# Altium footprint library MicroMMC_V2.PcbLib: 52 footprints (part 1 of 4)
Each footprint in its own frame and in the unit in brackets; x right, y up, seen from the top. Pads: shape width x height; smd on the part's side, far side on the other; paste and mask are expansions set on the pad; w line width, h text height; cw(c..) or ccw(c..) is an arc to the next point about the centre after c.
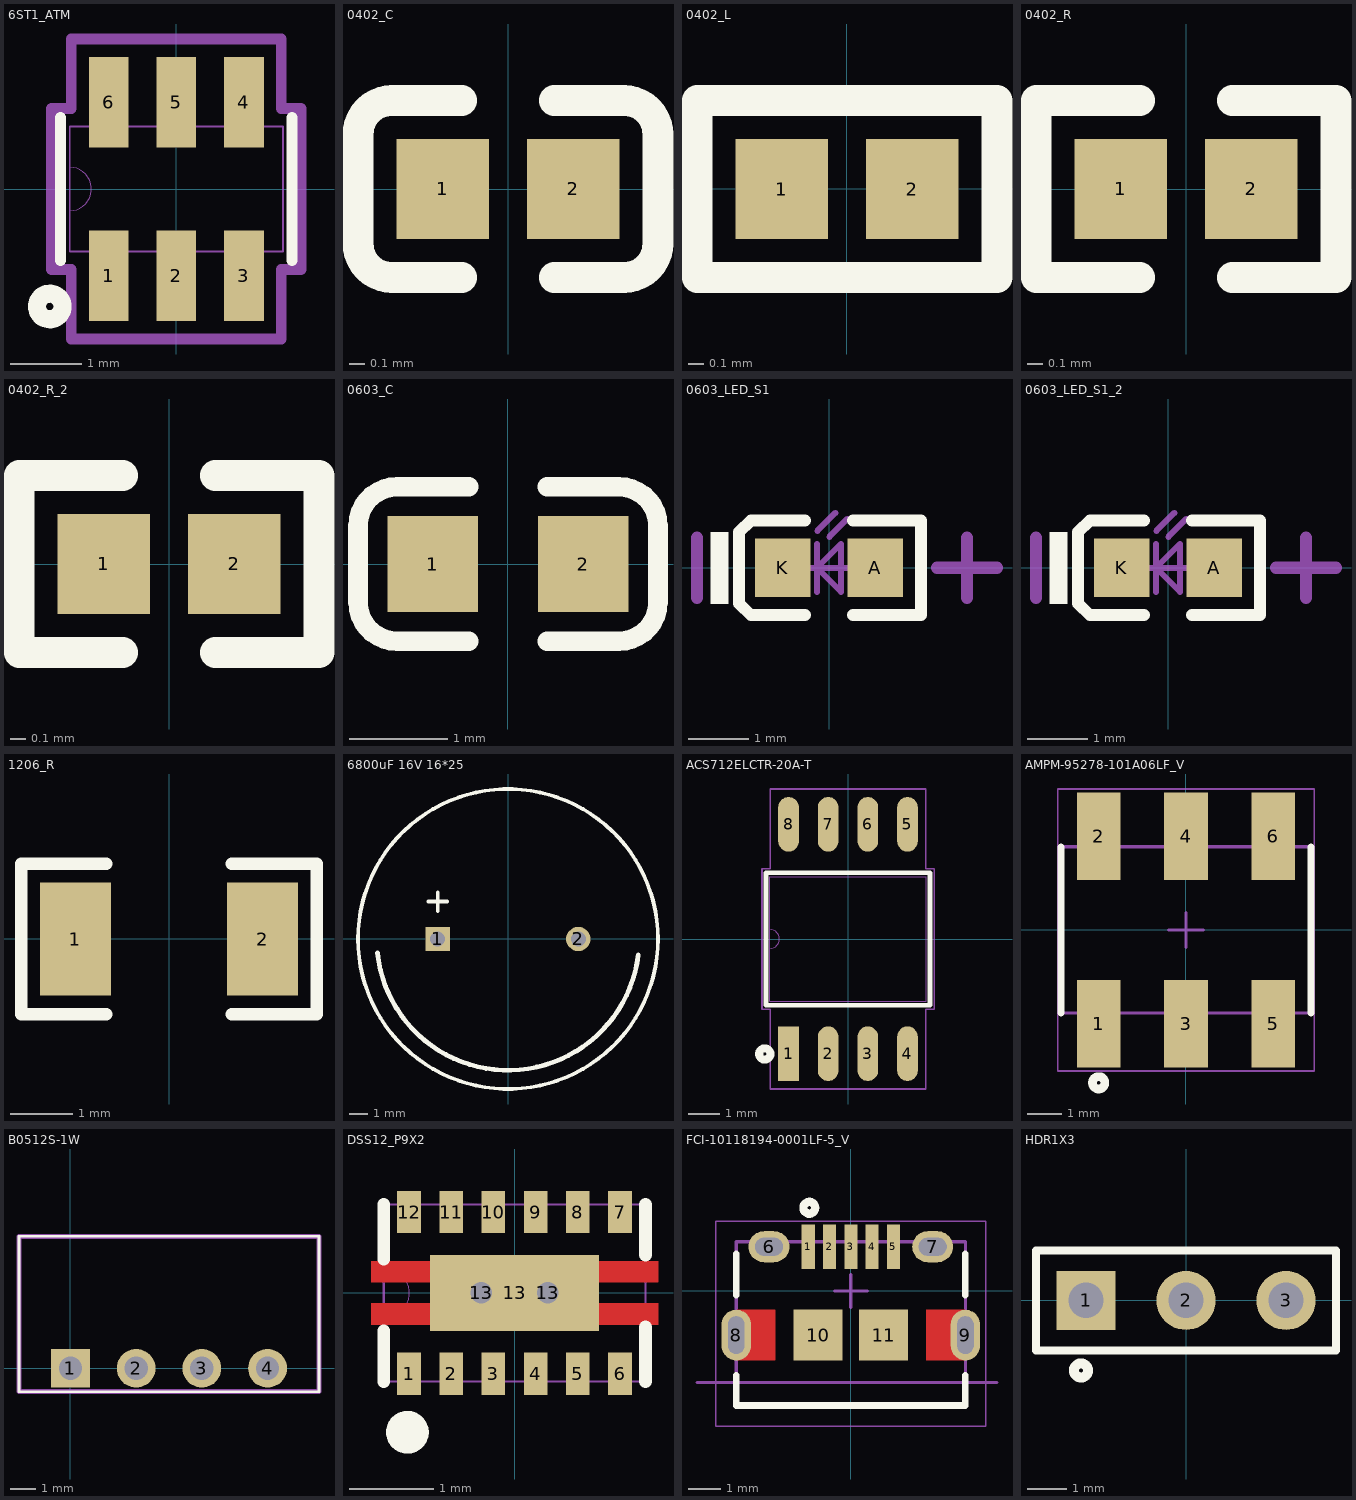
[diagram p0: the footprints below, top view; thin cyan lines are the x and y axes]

## 6ST1_ATM [mil] "ATTINY10"
pads (6):
  rect 22x50 smd: 1(-37.4,-48) 2(0,-48) 3(37.4,-48) 4(37.4,48) 5(0,48) 6(-37.4,48)
Top Overlay:
  circle w10: c-70,-65 r7.07
  lines w6: -64,-39.5 -64,39.5 ; 64,-39.5 64,39.5
Mechanical 13:
  lines w0: -59,-12 ccw(c-59,0) -59,12
  lines w1: -59,-34.5 -59,34.5 59,34.5 59,-34.5 -59,-34.5 ; -47.4,-59 -47.4,-34.5 -27.4,-34.5 -27.4,-59 -47.4,-59 ; -47.4,34.5 -27.4,34.5 -27.4,59 -47.4,59 -47.4,34.5 ; -10,-59 -10,-34.5 10,-34.5 10,-59 -10,-59 ; -10,34.5 10,34.5 10,59 -10,59 -10,34.5 ; 27.4,-59 27.4,-34.5 47.4,-34.5 47.4,-59 27.4,-59 ; 27.4,34.5 47.4,34.5 47.4,59 27.4,59 27.4,34.5
Mechanical 15:
  lines w6: -69,-44.5 -58.1,-44.5 -58.1,-83 58.1,-83 58.1,-44.5 69,-44.5 69,44.5 58.1,44.5 58.1,83 -58.1,83 -58.1,44.5 -69,44.5 -69,-44.5
3D body: height 10, standoff 0, extent -10,0 0,10
3D body "6ST1_ATM.step": height 58.11, standoff 0, extent -59.02,-59.01 59.01,59.02

## 0402_C [mm]
pads (2):
  rect 0.6x0.65 smd mask+0.051: 1(-0.425,0) 2(0.425,0)
Top Overlay:
  lines w0.2: -0.755,-0.575 cw(c-0.755,-0.355) -0.975,-0.355 -0.975,0.355 cw(c-0.755,0.355) -0.755,0.575 ; -0.75,-0.575 -0.3,-0.575 ; -0.75,0.575 -0.3,0.575 ; 0.3,-0.575 0.75,-0.575 ; 0.3,0.575 0.75,0.575 ; 0.755,-0.575 ccw(c0.755,-0.355) 0.975,-0.355 0.975,0.355 ccw(c0.755,0.355) 0.755,0.575
3D body "0402 SMD Capacitor.step": height 0.2, standoff 0, extent -0.483,-0.3 0.518,0.3

## 0402_L [mm]
pads (2):
  rect 0.6x0.65 smd: 1(-0.425,0) 2(0.425,0)
Top Overlay:
  lines w0.2: -0.975,-0.575 -0.975,0.575 0.975,0.575 0.975,-0.575 -0.975,-0.575
3D body "L0402.STEP": height 0.36, standoff -0.01, extent -0.49,-0.262 0.515,0.263

## 0402_R [mm]
pads (2):
  rect 0.6x0.65 smd mask+0.051: 1(-0.425,0) 2(0.425,0)
Top Overlay:
  lines w0.2: -0.3,-0.575 -0.975,-0.575 -0.975,0.575 -0.3,0.575 ; 0.3,-0.575 0.975,-0.575 0.975,0.575 0.3,0.575
3D body "User Library-RES_1005-0402.STEP": height 0.41, standoff 0, extent -0.575,-0.275 0.575,0.275

## 0402_R_2 [mm]
pads (2):
  rect 0.6x0.65 smd mask+0.051: 1(-0.425,0) 2(0.425,0)
Top Overlay:
  lines w0.2: -0.3,-0.575 -0.975,-0.575 -0.975,0.575 -0.3,0.575 ; 0.3,-0.575 0.975,-0.575 0.975,0.575 0.3,0.575
3D body "User Library-RES_1005-0402.STEP": height 0.41, standoff 0, extent -0.575,-0.275 0.575,0.275

## 0603_C [mm]
pads (2):
  rect 0.93x0.98 smd: 1(-0.77,0) 2(0.77,0)
Top Overlay:
  lines w0.2: -0.4,-0.79 -1.135,-0.79 cw(c-1.135,-0.39) -1.535,-0.39 -1.535,0.39 cw(c-1.135,0.39) -1.135,0.79 -0.4,0.79 ; 0.4,-0.79 1.135,-0.79 ccw(c1.135,-0.39) 1.535,-0.39 1.535,0.39 ccw(c1.135,0.39) 1.135,0.79 0.4,0.79
3D body "User Library-0603 SMD Capacitor.STEP": height 0.3, standoff 0, extent -0.8,-0.4 0.8,0.4

## 0603_LED_S1 [mm]
pads (2):
  rect 0.93x0.98 smd: A(0.77,0) K(-0.77,0)
Top Overlay:
  rectangle: -1.975,-0.6 -1.675,0.6
  lines w0.2: -0.4,-0.79 -1.3,-0.79 -1.5,-0.597 -1.5,0.597 -1.3,0.79 -0.4,0.79 ; 0.4,-0.79 1.535,-0.79 1.535,0.79 0.4,0.79
Mechanical 13:
  lines w0.1: -0.4,0 0.4,0 ; -0.2,-0.4 -0.2,0.4 ; -0.195,0.617 0.105,0.917 ; 0.005,0.517 0.305,0.817 ; -0.2,0 0.2,-0.4 0.2,0.4 -0.2,0
Mechanical 15:
  lines w0.203: -2.2,-0.5 -2.2,0.5 ; 1.8,0 2.8,0 ; 2.3,-0.5 2.3,0.5
3D body "User Library-LED_0603_R.STEP": height 0.6, standoff 0, extent -0.8,-0.4 0.8,0.4

## 0603_LED_S1_2 [mm]
pads (2):
  rect 0.93x0.98 smd: A(0.77,0) K(-0.77,0)
Top Overlay:
  rectangle: -1.975,-0.6 -1.675,0.6
  lines w0.2: -0.4,-0.79 -1.3,-0.79 -1.5,-0.597 -1.5,0.597 -1.3,0.79 -0.4,0.79 ; 0.4,-0.79 1.535,-0.79 1.535,0.79 0.4,0.79
Mechanical 13:
  lines w0.1: -0.4,0 0.4,0 ; -0.2,-0.4 -0.2,0.4 ; -0.195,0.617 0.105,0.917 ; 0.005,0.517 0.305,0.817 ; -0.2,0 0.2,0.4 0.2,-0.4 -0.2,0
Mechanical 15:
  lines w0.203: -2.2,-0.5 -2.2,0.5 ; 1.8,0 2.8,0 ; 2.3,-0.5 2.3,0.5
3D body "User Library-LED_0603_R.STEP": height 0.6, standoff 0, extent -0.8,-0.4 0.8,0.4

## 1206_R [mm]
pads (2):
  rect 1.13x1.8 smd: 1(-1.49,0) 2(1.49,0)
Top Overlay:
  lines w0.2: -1,-1.2 -2.355,-1.2 -2.355,1.2 -1,1.2 ; 1,-1.2 2.355,-1.2 2.355,1.2 1,1.2
3D body "User Library-RES_3216-1206.STEP": height 0.85, standoff 0, extent -1.7,-0.864 1.65,0.866

## 6800uF 16V 16*25 [mm] "LCSC C47893"
pads (2):
  rect 1.3x1.3 hole 0.8: 1(-3.75,0)
  round 1.3 hole 0.8: 2(3.75,0)
Top Overlay:
  circle w0.2: c0,0 r8
  lines w0.2: -4.25,2 -3.25,2 ; -3.75,1.5 -3.75,2.5
  lines w0.254: -6.96,-0.743 ccw(c0,0) 6.949,-0.844
3D body "ESK688M010AM2AA v1.step": height 32.01, standoff -19.99, extent -8,-8 8,8

## ACS712ELCTR-20A-T [mil]
pads (8):
  rect 26x69 smd paste+0 mask+0: 1(-75,-144.69)
  oval 26x69 smd paste+0 mask+0: 2(-25,-144.69) 3(25,-144.69) 4(75,-144.69) 5(75,144.69) 6(25,144.69) 7(-25,144.69) 8(-75,144.69)
Top Overlay:
  circle w10: c-105,-145 r7.07
  lines w6: -103.5,-83.5 -103.5,83.5 103.5,83.5 103.5,-83.5 -103.5,-83.5
Mechanical 13:
  lines w0: -98.5,-12 ccw(c-98.5,0) -98.5,12
  lines w1: -98.5,-78.5 -98.5,78.5 98.5,78.5 98.5,-78.5 -98.5,-78.5
Mechanical 15:
  lines w1.97: -108.5,-88.5 -108.5,88.5 -98,88.5 -98,189.19 98,189.19 98,88.5 108.5,88.5 108.5,-88.5 98,-88.5 98,-189.19 -98,-189.19 -98,-88.5 -108.5,-88.5
3D body "SOIC-8_ALM.step": height 69.09, standoff 0, extent -98.5,-170.4 98.5,160.39
3D body "SOIC-8_ALM.step": height 69.09, standoff 0, extent -98.5,-165.4 98.5,165.4
3D body "SOIC-8_ALM.step": height 69.09, standoff 0, extent -98.5,-165.39 98.5,165.4
3D body "SOIC-8_ALM.step": height 69.09, standoff 0, extent -98.5,-165.4 98.5,165.4
3D body: height 10, standoff 0, extent -10,0 0,10

## AMPM-95278-101A06LF_V [mil] "SMD, 6-Leads, Body 7.26x4.83mm, Pitch 2.54mm"
height 566.93
pads (6):
  rect 50x100 smd: 1(-100,-107.48) 2(-100,107.48) 3(0,-107.48) 4(0,107.48) 5(100,-107.48) 6(100,107.48)
Top Overlay:
  circle w10: c-100,-175 r7.07
  lines w7.87: -142.91,-95.08 -142.91,95.08 ; 142.91,-95.08 142.91,95.08
Mechanical 13:
  lines w3.94: -142.91,-95.08 -142.91,95.08 142.91,95.08 142.91,-95.08 -142.91,-95.08
Mechanical 15:
  lines w1.97: -146.85,-161.42 -146.85,161.42 146.85,161.42 146.85,-161.42 -146.85,-161.42
  lines w3.94: -19.68,0 19.68,0 ; 0,-19.68 0,19.69
3D body "95278_y01_06_asm.stp": height 382.38, standoff 1.99, extent -142.13,-143.43 142.12,143.42

## B0512S-1W [mm]
pads (4):
  rect 1.5x1.5 hole 0.9: 1(0,0)
  round 1.5 hole 0.9: 2(2.54,0) 3(5.08,0) 4(7.62,0)
Top Overlay:
  lines w0.1: -1.99,-0.9 -1.99,5.1 9.61,5.1 9.61,-0.9 -1.99,-0.9
Mechanical 13:
  lines w0.2: -1.99,-0.9 -1.99,5.1 9.61,5.1 9.61,-0.9 -1.99,-0.9
3D body "ROE-0512S.stp": height 10.6, standoff -5, extent -1.94,-0.9 9.56,5.1

## DSS12_P9X2 [mm]
pads (15):
  rect 0.28x0.5 smd: 1(-1.25,-0.959) 2(-0.75,-0.959) 3(-0.25,-0.959) 4(0.25,-0.959) 5(0.75,-0.959) 6(1.25,-0.959) 7(1.25,0.959) 8(0.75,0.959) 9(0.25,0.959) 10(-0.25,0.959) 11(-0.75,0.959) 12(-1.25,0.959)
  round 0.508 hole 0.254: 13(-0.394,0) 13(0.394,0)
  rect 2x0.9 smd paste-1 mask-0.991: 13(0,0)
Top Layer:
  region: -1,0
  region: 1,0
  region: -1,0.375 -1,0.125 -1.7,0.125 -1.7,0.375
  region: -1,-0.375 -1,-0.125 -1.7,-0.125 -1.7,-0.375
  region: 1,-0.375 1,-0.125 1.7,-0.125 1.7,-0.375
  region: 1,0.375 1,0.125 1.7,0.125 1.7,0.375
Top Overlay:
  circle w0.254: c-1.27,-1.651 r0.127
  lines w0.152: -1.55,-1.05 -1.55,-0.451 ; -1.55,0.402 -1.55,1.05 ; 1.55,-1.05 1.55,-0.402 ; 1.55,0.451 1.55,1.05
Top Paste:
  region: -1.365,-0.734 -1.365,-1.184 -1.135,-1.184 -1.135,-0.734
  region: -0.865,-0.734 -0.865,-1.184 -0.635,-1.184 -0.635,-0.734
  region: -0.365,-0.734 -0.365,-1.184 -0.135,-1.184 -0.135,-0.734
  region: 0.135,-0.734 0.135,-1.184 0.365,-1.184 0.365,-0.734
  region: 0.635,-0.734 0.635,-1.184 0.865,-1.184 0.865,-0.734
  region: 1.135,-0.734 1.135,-1.184 1.365,-1.184 1.365,-0.734
  region: 1.135,1.184 1.135,0.734 1.365,0.734 1.365,1.184
  region: 0.635,1.184 0.635,0.734 0.865,0.734 0.865,1.184
  region: 0.135,1.184 0.135,0.734 0.365,0.734 0.365,1.184
  region: -0.365,1.184 -0.365,0.734 -0.135,0.734 -0.135,1.184
  region: -0.865,1.184 -0.865,0.734 -0.635,0.734 -0.635,1.184
  region: -1.365,1.184 -1.365,0.734 -1.135,0.734 -1.135,1.184
  region: -1,0
  region: 1,0
  region: -1.051,0.324 -1.051,0.176 -1.649,0.176 -1.649,0.324
  region: -1.051,-0.324 -1.051,-0.176 -1.649,-0.176 -1.649,-0.324
  region: 1.051,-0.324 1.051,-0.176 1.649,-0.176 1.649,-0.324
  region: 1.051,0.324 1.051,0.176 1.649,0.176 1.649,0.324
  region: -0.925,-0.1 -0.925,-0.375 -0.494,-0.375 -0.494,-0.241 -0.635,-0.1
  region: -0.294,-0.241 -0.294,-0.375 0.294,-0.375 0.294,-0.241 0.152,-0.1 -0.152,-0.1
  region: 0.494,-0.241 0.494,-0.375 0.925,-0.375 0.925,-0.1 0.635,-0.1
  region: -0.925,0.375 -0.925,0.1 -0.635,0.1 -0.494,0.241 -0.494,0.375
  region: -0.294,0.375 -0.294,0.241 -0.152,0.1 0.152,0.1 0.294,0.241 0.294,0.375
  region: 0.494,0.375 0.494,0.241 0.635,0.1 0.925,0.1 0.925,0.375
Top Solder:
  region: -1.46,-0.639 -1.46,-1.279 -1.04,-1.279 -1.04,-0.639
  region: -0.96,-0.639 -0.96,-1.279 -0.54,-1.279 -0.54,-0.639
  region: 0.54,-0.639 0.54,-1.279 0.96,-1.279 0.96,-0.639
  region: 1.04,-0.639 1.04,-1.279 1.46,-1.279 1.46,-0.639
  region: 1.04,1.279 1.04,0.639 1.46,0.639 1.46,1.279
  region: 0.54,1.279 0.54,0.639 0.96,0.639 0.96,1.279
  region: 0.04,1.279 0.04,0.639 0.46,0.639 0.46,1.279
  region: -0.46,1.279 -0.46,0.639 -0.04,0.639 -0.04,1.279
  region: -0.96,1.279 -0.96,0.639 -0.54,0.639 -0.54,1.279
  region: -1.46,1.279 -1.46,0.639 -1.04,0.639 -1.04,1.279
  region: -1,0
  region: 1,0
  region: -1,0.375 -1,0.125 -1.7,0.125 -1.7,0.375
  region: -1,-0.375 -1,-0.125 -1.7,-0.125 -1.7,-0.375
  region: 1,-0.375 1,-0.125 1.7,-0.125 1.7,-0.375
  region: 1,0.375 1,0.125 1.7,0.125 1.7,0.375
  region: -0.594,-0.513 -1.064,-0.513 -1.064,0.513 -0.594,0.513
  region: 0.194,-0.513 -0.194,-0.513 -0.194,0.513 0.194,0.513
  region: 1.064,-0.513 0.594,-0.513 0.594,0.513 1.064,0.513
  region: 1.064,-0.513 -1.064,-0.513 -1.064,-0.2 1.064,-0.2
  region: 1.064,0.2 -1.064,0.2 -1.064,0.513 1.064,0.513
  region: 0.04,-0.639 0.04,-1.279 0.46,-1.279 0.46,-0.639
  region: -0.46,-0.639 -0.46,-1.279 -0.04,-1.279 -0.04,-0.639
Mechanical 13:
  lines w0: -1.55,-0.305 ccw(c-1.55,0) -1.55,0.305
  lines w0.025: -1.55,-1.05 -1.55,1.05 1.55,1.05 1.55,-1.05 -1.55,-1.05 ; -1.4,-1.05 -1.1,-1.05 -1.4,-1.05 ; -1.4,1.05 -1.1,1.05 -1.4,1.05 ; -0.9,-1.05 -0.6,-1.05 -0.9,-1.05 ; -0.9,1.05 -0.6,1.05 -0.9,1.05 ; -0.4,-1.05 -0.1,-1.05 -0.4,-1.05 ; -0.4,1.05 -0.1,1.05 -0.4,1.05 ; 0.1,-1.05 0.4,-1.05 0.1,-1.05 ; 0.1,1.05 0.4,1.05 0.1,1.05 ; 0.6,-1.05 0.9,-1.05 0.6,-1.05 ; 0.6,1.05 0.9,1.05 0.6,1.05 ; 1.1,-1.05 1.4,-1.05 1.1,-1.05 ; 1.1,1.05 1.4,1.05 1.1,1.05
3D body "DSS12_P9X2.step": height 1.7, standoff 0.2, extent -1.7,-1.05 1.7,1.05
3D body: height 0.25, standoff 0, extent -0.254,0 0,0.254

## FCI-10118194-0001LF-5_V [mm] "SMD, 5-Leads, Body 7x5mm, Pitch 0.65 mm"
height 2.673
pads (11):
  rect 0.4x1.35 smd: 1(-1.3,1.35) 2(-0.65,1.35) 3(0,1.35) 4(0.65,1.35) 5(1.3,1.35)
  oval 1.25x0.95 hole 0.55 slot 0.85 at 0 deg: 6(-2.5,1.35) 7(2.5,1.35)
  oval 0.9x1.55 hole 0.5 slot 1.15 at 90 deg: 8(-3.5,-1.35) 9(3.5,-1.35)
  rect 1.5x1.55 smd: 10(-1,-1.35) 11(1,-1.35)
Top Layer:
  region: 3.5,-2.125 3.5,-0.575 2.3,-0.575 2.3,-2.125
  region: -2.3,-2.125 -2.3,-0.575 -3.5,-0.575 -3.5,-2.125
Top Overlay:
  circle w0.254: c-1.27,2.54 r0.18
  lines w0.2: -3.5,-2.575 -3.5,-3.5 3.5,-3.5 3.5,-2.575 ; -3.5,-0.125 -3.5,1.13 ; 3.5,-0.125 3.5,1.13
Mechanical 6:
  lines w0.1: -4.7,-2.8 4.465,-2.8
  text "PCB EDGE" at -7.2,-2.9 h0.3
Mechanical 13:
  lines w0.1: -3.5,-3.5 -3.5,1.5 3.5,1.5 3.5,-3.5 -3.5,-3.5
Mechanical 15:
  lines w0.05: -4.125,-4.13 -4.125,2.125 4.125,2.125 4.125,-4.13 -4.125,-4.13
  lines w0.1: -0.5,0 0.5,0 ; 0,-0.5 0,0.5
3D body "10118194c.stp": height 2.72, standoff -0.55, extent -4.025,-4.03 4.025,1.55

## HDR1X3 [mm] "Connector; Header; 3 Position"
pads (3):
  rect 1.5x1.5 hole 0.9: 1(-2.54,0)
  round 1.5 hole 0.9: 2(0,0) 3(2.54,0)
Top Overlay:
  circle w0.254: c-2.667,-1.778 r0.18
  lines w0.2: -3.81,-1.27 3.81,-1.27 3.81,1.27 -3.81,1.27 -3.81,-1.27
3D body: height 0.25, standoff 0, extent -1272.54,-1272.537 -1267.46,-1267.463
